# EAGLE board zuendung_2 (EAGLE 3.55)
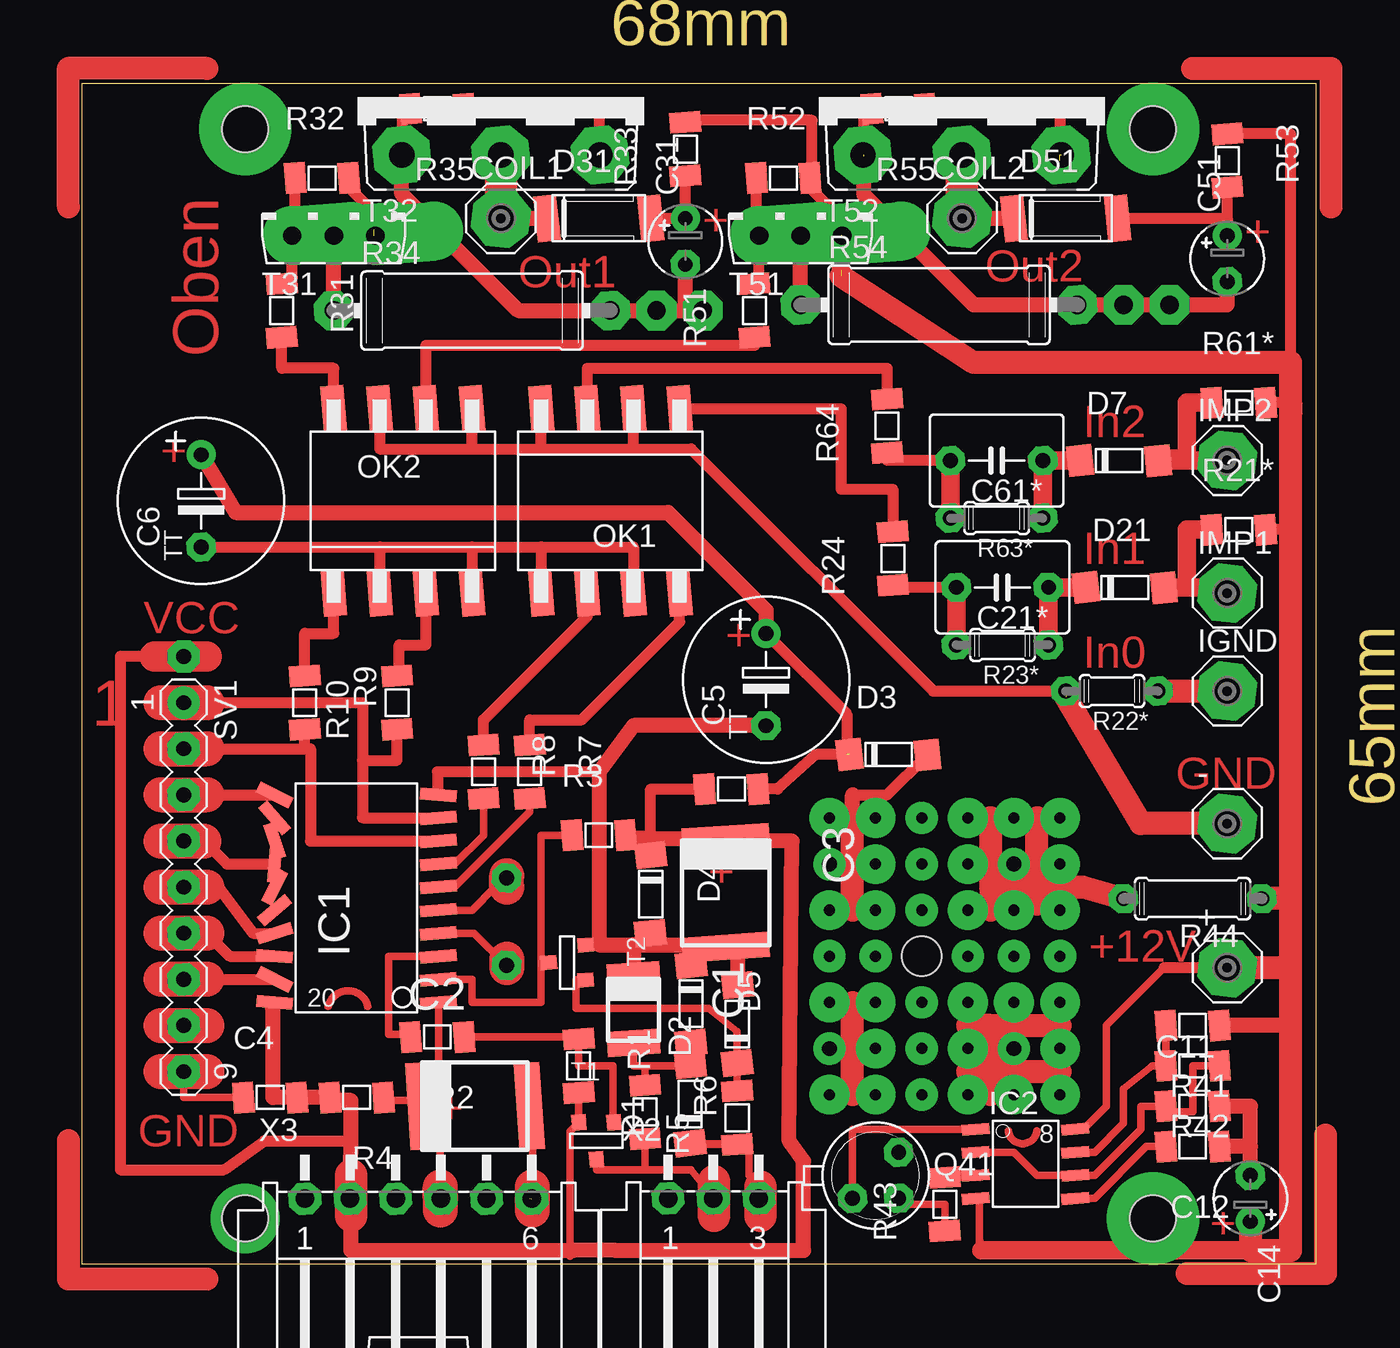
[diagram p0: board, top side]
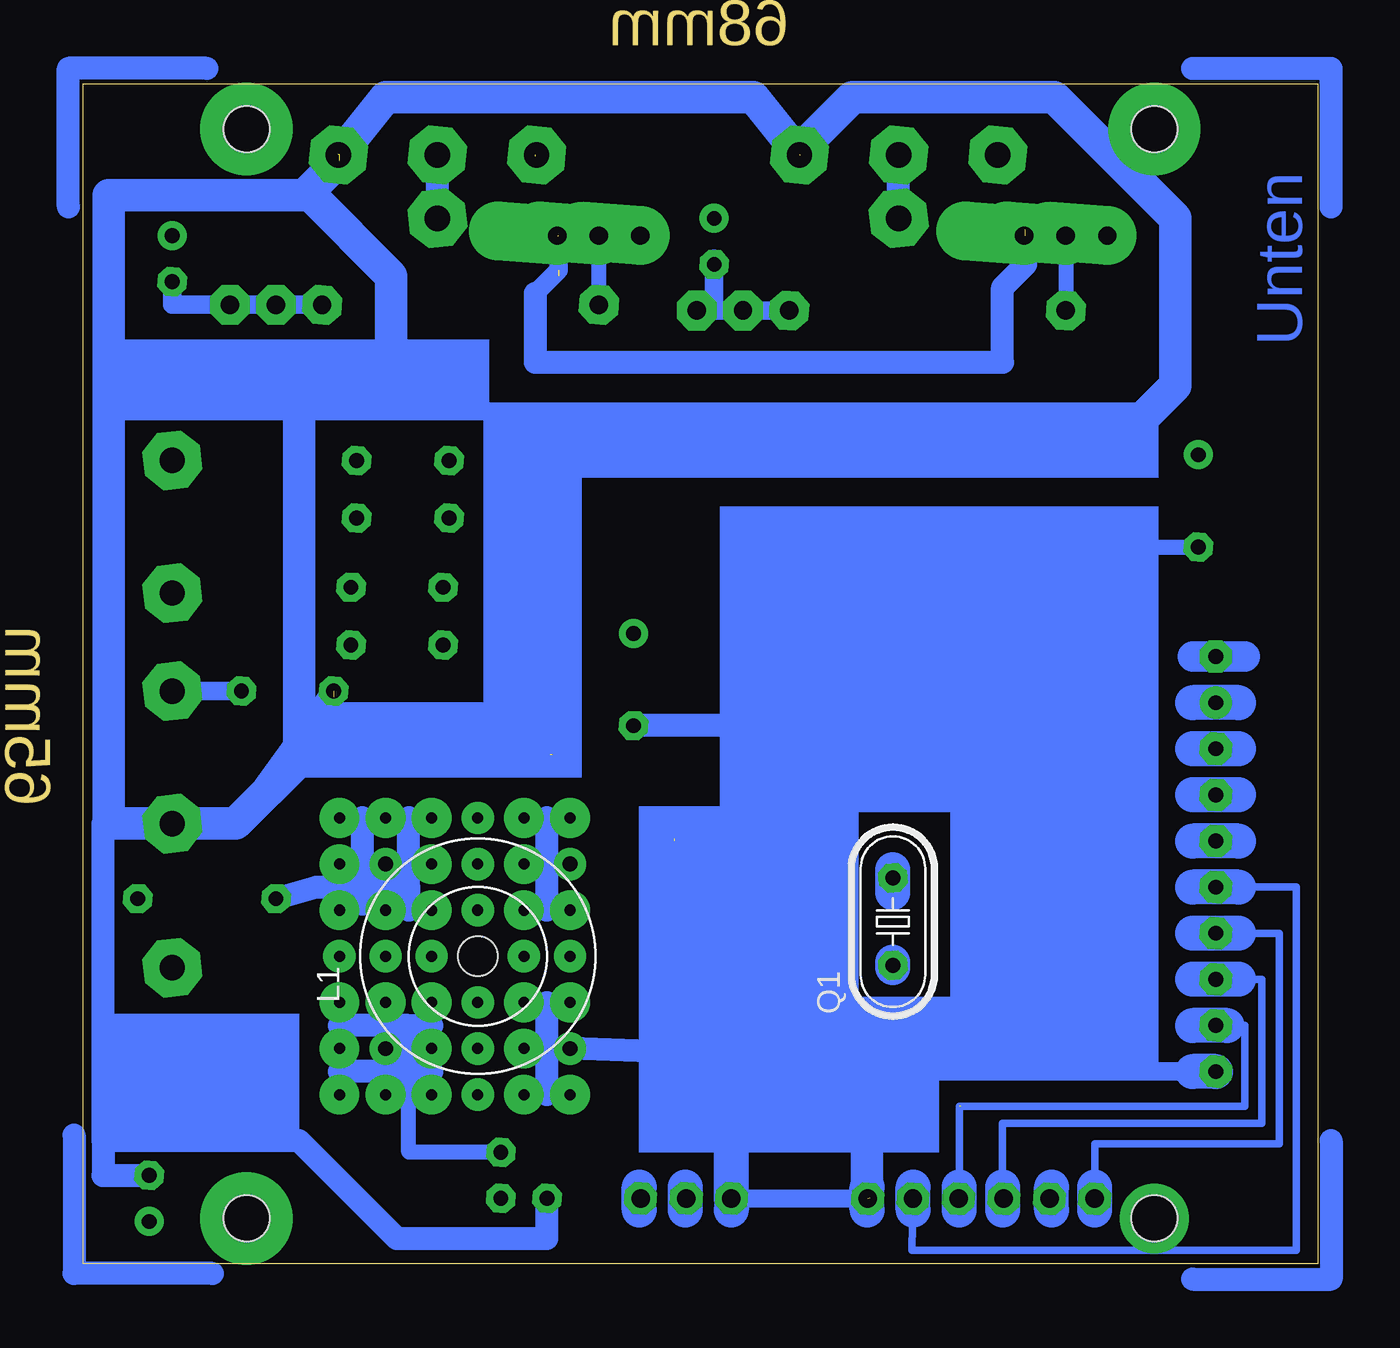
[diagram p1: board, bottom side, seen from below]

Size 68 x 65 mm. Coordinates in mm from the lower left corner, seen from the top.
Outline: 0,0 68,0 68,65 0,65 0,0
Copper layers used: Top, Bottom
Holes 2.54 mm at 9,2.5 59,2.5 59,62.5 9,62.5

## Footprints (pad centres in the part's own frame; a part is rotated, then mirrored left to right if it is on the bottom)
14E = drill 1.397 pad 3.175 octagon:  0,0
 = smd 1.4 x 2.9 rotated 3.8:  -1.8,0 | smd 1.4 x 2.9 rotated 4:  1.9,0
KO6X5 = smd 1.4 x 4.8 rotated 3.8:  -3,0 | smd 1.4 x 4.8 rotated 4:  3,0
06 = smd 1.143 x 1.702 rotated 4.4:  1.473,0 | smd 1.143 x 1.702 rotated 4.3:  -1.473,0
5D9 = drill 0.813 pad 1.6 octagon:  -2.54,0 | drill 0.813 pad 1.6 round:  2.54,0
2D4 = drill 0.813 pad 1.6 octagon:  -1.27,0 | drill 0.813 pad 1.6 round:  1.27,0
B5 = drill 0.813 pad 1.6 octagon:  -2.54,0;  2.54,0
D-80 = smd 1.397 x 1.702 rotated 6.6:  -2.388,0 | smd 1.397 x 1.702 rotated 5.7:  1.905,-0.025
LF = smd 1.27 x 2.54 rotated 6.6:  -2.857,0 | smd 1.27 x 2.54 rotated 5.7:  2.857,0
-20 = smd 0.66 x 2.007 rotated 4.3:  -5.08,-4.496;  6.35,-4.496 | smd 0.66 x 2.007 rotated 4.4:  -3.81,-4.496;  -5.08,4.521 | smd 0.66 x 2.007 rotated 4.5:  -2.54,-4.496 | smd 0.66 x 2.007 rotated 4.6:  -1.27,-4.496 | smd 0.66 x 2.007 rotated 4.7:  0,-4.496;  1.27,-4.496 | smd 0.66 x 2.007 rotated 4.8:  2.54,-4.496 | smd 0.66 x 2.007 rotated 4.9:  3.81,-4.496 | smd 0.66 x 2.007 rotated 5:  5.08,-4.496 | smd 0.66 x 2.007 rotated 49.3:  5.08,4.521 | smd 0.66 x 2.007 rotated 26.8:  6.35,4.521 | smd 0.66 x 2.007 rotated 71.8:  3.81,4.521 | smd 0.66 x 2.007 rotated 94.3:  2.54,4.521 | smd 0.66 x 2.007 rotated 116.8:  1.27,4.521 | smd 0.66 x 2.007 rotated 139.3:  0,4.521 | smd 0.66 x 2.007 rotated 161.8:  -1.27,4.521 | smd 0.66 x 2.007 rotated 184.3:  -2.54,4.521 | smd 0.66 x 2.007 rotated 206.8:  -3.81,4.521
-8 = smd 0.61 x 1.524 rotated 4.3:  -1.27,-2.743 | smd 0.61 x 1.524 rotated 4.9:  -1.27,2.743 | smd 0.61 x 1.524 rotated 4.4:  0,-2.743 | smd 0.61 x 1.524 rotated 4.5:  1.27,-2.743 | smd 0.61 x 1.524 rotated 4.8:  0,2.743 | smd 0.61 x 1.524 rotated 4.7:  1.27,2.743;  2.54,2.743 | smd 0.61 x 1.524 rotated 4.6:  2.54,-2.743
10X10 = drill 0.813 pad 1.778 round:  -5.08,5.08;  5.08,5.08;  5.08,-5.08;  -5.08,-5.08 | hole 2.184: 0,0
L08SO = smd 1.27 x 2.54 rotated 4.9:  -3.81,5.08 | smd 1.27 x 2.54 rotated 4.8:  -1.27,5.08 | smd 1.27 x 2.54 rotated 4.7:  1.27,5.08;  3.81,5.08 | smd 1.27 x 2.54 rotated 4.3:  -3.81,-5.08 | smd 1.27 x 2.54 rotated 4.4:  -1.27,-5.08 | smd 1.27 x 2.54 rotated 4.5:  1.27,-5.08 | smd 1.27 x 2.54 rotated 4.6:  3.81,-5.08
49U-V = drill 0.813 pad 1.6 octagon:  -2.413,0;  2.413,0
18 = drill 0.813 pad 1.6 octagon:  -1.27,-1.27;  1.27,-1.27;  1.27,1.27
04/5 = drill 0.813 pad 1.6 octagon:  -2.54,0;  2.54,0
14/15 = drill 1.016 pad 2.159 octagon:  -7.62,0;  7.62,0
07/7 = drill 0.813 pad 1.6 octagon:  -3.81,0;  3.81,0
09-1 = drill 0.813 pad 1.778 round:  -10.16,0 | drill 0.813 pad 1.778 octagon:  -7.62,0;  -5.08,0;  -2.54,0;  0,0;  2.54,0;  5.08,0;  7.62,0;  10.16,0
T-23 = smd 0.787 x 0.889 rotated 4.4:  0.991,1.016 | smd 0.787 x 0.889 rotated 4.3:  -0.94,1.016 | smd 0.787 x 0.889 rotated 4.5:  0.025,-1.016
126V = drill 1.016 pad 3.251 offset:  -2.286,-1.27;  0,-1.27;  2.286,-1.27
P3V = drill 1.397 pad 3.15 octagon:  -5.461,-3.175;  0,-3.175;  5.461,-3.175
FW3 = drill 1.016 pad 1.778 octagon:  0,1.905;  2.489,1.905;  5.004,1.905
FW6 = drill 1.016 pad 1.778 octagon:  0,1.905;  2.489,1.905;  5.004,1.905;  7.493,1.905;  10.008,1.905;  12.497,1.905

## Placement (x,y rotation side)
+  SE14E  [14E]  63.09,16.3 0 top
-  SE14E  [14E]  63.09,24.24 0 top
C1  2æ2/16  []  30.38,14.08 270 top
C2  22/16  [KO6X5]  21.65,8.68 0 top
C3  22/10  [KO6X5]  35.47,20.43 270 top
C4  100n  [06]  10.38,9.16 0 top
C5  470/10  [5D9]  37.69,32.18 90 top
C6  470/10  [5D9]  6.57,42.02 90 top
C11  2n7  [06]  61.18,8.68 0 top
C12  10n  [06]  61.18,6.46 180 top
C14  47/25  [2D4]  64.36,3.61 270 top
C21*  220n*  [B5]  50.7,37.26 180 top
C31  0,22  [2D4]  33.24,56.31 90 top
C51  0,22  [2D4]  63.09,55.36 90 top
C61*  220n*  [B5]  50.39,44.24 180 top
COIL1  SE14E  [14E]  23.08,57.58 0 top
COIL2  SE14E  [14E]  48.48,57.58 0 top
D1  LL4148  [D-80]  33.5,9.03 90 top
D2  LL4148  [D-80]  36.1,13.45 90 top
D3  LL4148  [D-80]  44.67,28.05 0 top
D4  5V1  [D-80]  31.34,20.11 270 top
D5  LL4148  [D-80]  33.56,14.08 270 top
D7  LL4148  [D-80]  57.37,44.24 0 top
D21  LL4148  [D-80]  57.69,37.26 0 top
D31  BYM10  [LF]  28.48,57.58 0 top
D51  BYM10  [LF]  54.2,57.58 0 top
IC1  AT90S2313  [-20]  15.14,19.48 90 top
IC2  ICM7555  [-8]  51.98,6.14 270 top
IGND  SE14E  [14E]  63.09,31.55 0 top
IMP1  SE14E  [14E]  63.09,36.94 0 top
IMP2  SE14E  [14E]  63.09,44.24 0 top
L1  T1:1/10  [10X10]  46.26,16.94 90 bottom
OK1  TLP759  [L08SO]  29.11,42.02 180 top
OK2  TLP759  [L08SO]  17.68,42.02 0 top
Q1  10.000  [49U-V]  23.4,18.84 90 bottom
Q41  BCY59  [18]  43.72,4.88 0 top
R1  4K7  [06]  27.37,10.91 270 top
R2  4K7  [06]  19.59,12.49 180 top
R3  4K7  [06]  28.48,23.61 0 top
R4  10K  [06]  15.14,9.16 180 top
R5  4K7  [06]  36.1,8.05 90 top
R6  4K7  [06]  31.02,8.37 270 top
R7  1K  [06]  24.67,27.1 270 top
R8  1k  [06]  22.13,27.1 270 top
R9  680  [06]  12.29,30.91 270 top
R10  680  [06]  17.37,30.91 90 top
R21*  12K*  [06]  63.72,40.44 0 top
R22*  0*  [04/5]  56.74,31.55 180 top
R23*  100K*  [04/5]  50.7,34.09 180 top
R24  330  [06]  44.67,38.85 90 top
R31  330  [06]  11.02,52.5 270 top
R32  1k  [06]  13.24,59.8 0 top
R33  270  [06]  33.24,61.39 90 top
R34  120/1  [14/15]  21.5,52.5 0 top
R35  1k2  [06]  19.59,63.61 180 top
R41  1k5  [06]  61.18,13.13 180 top
R42  1k5  [06]  61.18,10.91 180 top
R43  3K3  [06]  47.53,3.29 90 top
R44  56  [07/7]  61.18,20.11 180 top
R45  10  [06]  35.78,26.15 180 top
R51  330  [06]  37.05,52.5 90 top
R52  1k  [06]  38.64,59.8 0 top
R53  270  [06]  63.09,60.75 270 top
R54  120/1  [14/15]  47.21,52.82 0 top
R55  1k2  [06]  44.99,63.61 180 top
R61*  12k*  [06]  63.72,47.42 0 top
R63*  100k*  [04/5]  50.39,41.07 180 top
R64  330  [06]  44.35,46.15 90 top
SV1  MA09-1  [09-1]  5.62,20.75 270 top
T1  BC807  [T-23]  28.32,6.78 0 top
T2  BC817  [T-23]  26.73,16.62 270 top
T31  BD236_V  [126V]  13.88,57.9 0 top
T32  BD249_V  [P3V]  23.08,64.25 0 top
T51  BD236_V  [126V]  39.59,57.9 0 top
T52  BD249_V  [P3V]  48.48,64.25 0 top
U$8  [2]  -0.09,-0.21 0 top
U$9  [2]  67.85,0.11 90 top
U$10  [2]  68.17,65.2 180 top
U$11  [2]  -0.09,65.2 270 top
X2  MSFW3  [FW3]  32.29,1.7 0 top
X3  MSFW6  [FW6]  12.29,1.68 0 top

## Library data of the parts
+ - COIL1 COIL2 IGND IMP1 IMP2 = SOLPAD
C1-C4 C11 C12 D1-D5 D7 D21 D31 D51 R1-R10 R21* R24 R31-R33 R35 R41-R43 R45 R51-R53 R55 R61* R64 T1 T2 = SMD
C5 C6 C14 C31 C51 = CAP-TANT
C21* C61* = CAP
IC1 IC2 = SMD-IC
L1 = TRAFO-R
OK1 OK2 = OPTOCPL
Q1 = QUARTZ
Q41 T32 T52 = NPN
R22* R23* R34 R44 R54 R63* = R
SV1 = CON-LSTB
T31 T51 = PNP
U$8-U$11 = MARKS
X2 X3 = CON-MSF

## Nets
+12V: +. C14. IC2. R21*. R32. R33. R41. R44. R52. R53. R61*. T31. T51.
BT1: R1. R2. T1.
BT2: D2. R5. T2.
D21K: C21*. D21. R23*.
DGND: C1. C2. C3. C4. C5. C6. D2. D4. D5. IC1. L1. OK1. OK2. SV1. T2. X2. X3.
GND: -. C11. C12. C14. IC2. OK1. OK2. Q41. R22*. R35. R55. T32. T52.
INT0: OK1. R7.
MISO: IC1. SV1. X3.
MOSI: IC1. SV1. X3.
N$1: C31. D31. R33.
N$2: R31. R32. T31.
N$3: OK2. R31.
N$4: IC2. R43.
N$5: C12. IC2.
N$6: L1. R44.
N$7: C5. C6. D3. R45.
N$8: OK1. R24.
N$9: R34. T31.
N$10: C31. R34. R35. T32.
N$11: D3. L1.
N$14: C11. IC2. R42.
N$15: IC2. R41. R42.
N$16: C1. D1. D5. R6.
N$29: C21*. R23*. R24.
N$46: L1. Q41.
N$48: Q41. R43.
N$92: OK2. R51.
N$93: OK2. R10.
N$94: OK1. R64.
N$96: IC1. R8.
N$102: OK1. R8.
N$103: R54. T51.
N$104: R51. R52. T51.
N$105: COIL2. D51. T52.
N$106: C51. R54. R55. T52.
N$107: C51. D51. R53.
N$108: D7. IMP2. R61*.
N$109: C61*. R63*. R64.
N$111: C61*. D7. R63*.
OUT0: OK2. R9.
PB2: IC1. SV1.
PD0: IC1. R3. T2.
PD1: IC1. R2.
PD2: IC1. R7.
PD4: IC1. R9. SV1.
PD5: IC1. R10. SV1.
PD6: IC1. SV1.
RESET: C2. IC1. R4. SV1. X3.
RXD: D1. R5. X2.
SCK: IC1. SV1. X3.
TXD: R6. T1. X2.
VCC: C3. C4. D4. IC1. R1. R3. R4. R45. T1. X3.
X6: COIL1. D31. T32.
X21: D21. IMP1. R21*.
X22: IGND. R22*.
XTAL1: IC1. Q1.
XTAL2: IC1. Q1.

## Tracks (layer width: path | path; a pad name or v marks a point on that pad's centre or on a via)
+12V  (3 unrouted)
  Top 0.406: 49.44,1.38 49.44,1.06 | 49.44,1.38 49.55,0.75 | 49.23,3.61 49.44,3.61 49.44,1.38 | 54.72,7.41 55.15,7.41 56.42,8.68 56.42,13.13 59.59,16.3
  Top 0.61: 66.58,47.42 65.2,47.42 | 66.58,40.44 65.2,40.44 | +. 59.59,16.3 | 41.81,57.58 40.11,59.28 40.11,59.8 40.23,59.8 40.23,62.98 33.24,62.98 33.24,62.86 | 14.71,59.8 14.71,59.28 16.1,57.9 16.1,56.63 T31. | R53. 66.58,62.23 66.58,49.64
  Top 0.813: 66.58,13.13 R41.
  Top 1.016: 49.55,0.75 64.36,0.75 | 41.81,54.41 41.81,56.63 41.81,57.58
  Top 1.27: C14. 64.36,0.75 66.58,0.75 66.58,13.13 66.58,16.3 | 66.58,20.11 66.58,40.44 66.58,47.42 | 66.58,47.42 66.58,46.78 | 66.58,47.42 66.58,49.64 49.12,49.64 41.81,54.41 | 66.58,20.11 64.99,20.11 | 66.58,16.3 66.58,20.11 | 66.58,16.3 +.
  Bottom 1.016: 43.09,53.45 41.81,54.72 41.81,56.94
  Bottom 1.27: 43.09,53.45 43.09,49.64 17.37,49.64 17.37,53.77 16.1,55.04 16.1,56.94
BT1
  Top 0.406: 27.37,12.5 27.53,12.5 | 27.37,12.5 R1. 27.37,10.91 29.27,10.91 29.27,7.73 29.31,7.73 29.31,7.8 | R2. | R2. 27.37,12.5
BT2
  Top 0.406: 36.1,9.52 36.1,11.06 36.1,12.81 34.51,14.08 27.21,14.08 27.21,15.63 27.75,15.63
D21K
  Top 1.016: 55.3,37.26 53.24,37.26 53.24,34.09
DGND  (1 unrouted)
  Top 0.406: SV1. 5.62,9.16 C4. | C2. 24.83,10.43 24.83,3.76 24.67,3.61 | 27.75,17.56 28.23,17.57 28.48,17.57 | 31.66,17.57 D4. | 35.47,17.57 36.12,17.57
  Top 0.61: 6.57,39.48 16.41,39.48 | 16.41,39.48 16.41,36.94 | 16.41,39.48 21.5,39.48 | 21.5,39.48 OK2. | 21.5,39.48 25.3,39.48 | 25.3,39.48 25.3,36.94 | 25.3,39.48 30.38,39.48 30.38,36.94 | 28.48,27.1 19.59,27.1 19.59,25.83 19.64,25.83
  Top 0.813: 36.12,17.57 D2. | 30.38,17.57 30.38,15.88 | 30.38,17.57 31.66,17.57 35.47,17.57 | 30.38,17.57 28.48,17.57 28.48,27.1 30.38,29.64 37.69,29.64 | 35.47,17.57 C3. | 33.56,16.47 33.56,17.57 35.47,17.57
  Bottom 0.406: 24.83,3.61 X3. 24.99,3.59 24.99,3.61 24.67,3.61 | 32.29,3.61 32.29,11.54
  Bottom 0.813: 6.57,39.48 9.43,39.48 9.43,36.31 15.14,29.64 37.69,29.64
  Bottom 1.016: 6.89,10.59 24.83,10.59 | X3. 32.29,3.61 | 32.29,21.38 28.48,21.38
  Bottom 1.27: 37.69,29.64 32.29,29.64 32.29,21.38 | 32.29,11.54 L1.
  Bottom 1.778: 24.83,10.59 24.83,3.61
  Bottom 1.93: 32.29,21.38 32.29,3.61 32.29,2.97 | SV1. 6.89,10.59
GND  (4 unrouted)
  Top 0.406: 42.45,3.61 42.45,7.41 49.23,7.41 49.44,7.41
  Top 0.61: 25.3,44.88 30.38,44.88 | 25.3,44.88 OK1. | 21.5,44.88 25.3,44.88 | 21.5,44.88 21.5,47.1 | 21.5,44.88 16.41,44.88 16.41,47.1 | 30.38,44.88 30.38,47.1 | 30.38,44.88 33.56,44.88 46.9,31.55 R22*. | R35. 28.48,63.61 28.48,61.07 | R55. 53.88,63.61 53.88,60.75
  Top 0.813: 62.66,8.68 64.36,8.68 64.36,6.46 | 64.36,6.46 C12. | 64.36,4.88 64.36,6.46
  Top 1.27: 54.2,31.23 58.33,24.24 -.
  Bottom 1.27: R22*. 59.28,24.51 | 66.9,6.78 66.9,24.24 66.58,24.24 | 66.9,6.78 66.9,4.88 64.36,4.88 | 42.45,3.61 42.45,1.38 50.7,1.38 56.1,6.78 66.9,6.78 | T32. 28.48,61.07 | 53.56,61.07 T52.
  Bottom 1.778: T32. 31.08,64.25 51.34,64.25 53.88,61.07 | 63.41,24.24 66.58,24.24 66.58,58.85 55.78,58.85 53.56,61.07 | 63.41,24.24 -. | 63.41,24.24 59.59,24.24 56.1,27.73 56.1,48.37
INT0
  Top 0.61: 32.92,36.94 32.92,35.35 27.53,29.96 24.67,29.96 R7.
MISO
  Top 0.406: 5.62,18.21 6.89,18.21 | 10.62,16.94 10.7,16.94
  Top 0.61: 6.89,18.21 8.16,16.94 10.62,16.94
  Top 1.93: 6.89,18.21 4.35,18.21
  Bottom 0.406: 5.62,18.21 4.35,18.21 2.13,18.21 2.13,6.62 12.29,6.62 12.29,3.59
  Bottom 1.93: 4.35,18.21 6.89,18.21
MOSI
  Top 0.406: 5.62,20.75 7.53,20.75
  Top 0.61: 7.53,20.75 9.43,18.21 10.62,18.21
  Bottom 0.406: 22.3,3.59 22.36,0.75 1.17,0.75 1.17,20.75 4.35,20.75 5.62,20.75
  Bottom 1.93: 4.35,20.75 6.89,20.75
N$1
  Top 0.61: D31. C31. R33.
N$2
  Top 0.61: R32. 11.77,56.74 11.65,56.63 11.59,56.63 11.59,54.34 11.02,53.77 R31.
N$3
  Top 0.61: 11.02,51.03 11.02,49.33 13.88,49.33 13.88,47.1
N$4
  Top 0.406: 47.53,4.76 47.53,4.88
  Top 0.61: 49.44,4.88 49.23,4.88 47.53,4.88
N$5
  Top 0.406: 59.71,6.46 58.64,6.46 55.78,3.61 IC2. 54.52,3.61
N$6
  Top 0.813: 51.66,20.75 51.34,21.07 51.34,22.02
  Top 1.27: R44. 55.15,20.75 51.66,20.75
  Bottom 1.27: 54.2,20.75 55.15,20.75 R44.
N$7  (1 unrouted)
  Top 0.61: R45. 38.32,26.15 40.43,28.05 42.13,28.05 42.13,30.27 C5.
  Top 0.813: C5. 37.69,35.99 32.29,41.39 8.48,41.39 C6.
N$8
  Top 0.61: 32.92,47.1 41.81,47.1 41.81,42.66 44.67,42.66 44.67,40.32
N$9
  Top 0.813: 13.88,52.5 13.88,56.63
  Bottom 0.813: 13.88,52.5 13.56,52.5 13.88,52.82 13.88,56.63
N$10  (via drill 1.02 pad 2.18)
  Top 0.61: 18.12,63.61 17.68,63.61 17.68,61.07
  Top 0.813: 17.68,61.07 17.62,61.07 17.62,58.91 24.04,52.5 R34. v34.2,52.5 33.24,52.5 33.24,55.04
  Bottom 1.016: R34. 33.24,52.5 | 33.24,55.36 33.24,55.04 33.24,52.5 | 33.24,52.5 v34.2,52.5
N$11
  Top 0.61: D3. 44.35,25.83 42.45,25.83
  Top 0.813: 42.45,25.83 42.45,22.02 41.18,22.02
N$12  (via drill 0.61 pad 2.18)
  other vias: 43.72,22.02
N$13
  Top 1.93: 4.35,20.75 6.89,20.75
N$14
  Top 0.406: R42. 61.18,10.91 61.18,8.37 59.59,8.37 59.59,8.68 C11. 58.33,8.68 58.33,7.41 55.78,4.88 54.52,4.88 | 49.23,6.14 51.34,6.14 52.61,4.88 54.52,4.88 | 54.52,4.88 54.72,4.88
N$15
  Top 0.406: 59.71,10.91 59.71,13.13 | 59.71,10.91 59.59,10.91 | 59.71,10.91 58.96,10.91 57.37,9.64 57.37,7.73 55.78,6.14 54.72,6.14 54.52,6.14
N$16
  Top 0.406: 31.02,10.91 30.38,10.91 C1. | 31.02,10.91 R6. | 31.02,10.91 33.56,10.91
  Top 0.813: D1. 33.56,10.91 33.53,10.91 D5.
N$17
  Top 1.93: 4.35,13.13 6.89,13.13
N$18
  Top 1.93: 4.35,10.59 6.89,10.59
N$19
  Top 1.93: 23.4,16.78 23.4,16.3
N$20  (via drill 0.61 pad 2.18)
  other vias: 48.8,22.02
N$21
  Bottom 1.93: 12.29,2.97 12.29,4.24
N$22
  Bottom 1.93: 14.67,2.97 14.67,4.24
N$23
  Bottom 1.93: 19.75,2.97 19.75,4.24
N$24
  Bottom 1.93: 22.29,2.97 22.29,4.24
N$25
  Bottom 1.93: 24.83,2.97 24.83,4.24
N$26
  Bottom 1.93: 34.83,2.97 34.83,4.24
N$27
  Bottom 1.93: 37.37,2.97 37.37,4.24
N$28
  Bottom 1.93: 4.35,30.91 6.89,30.91
N$29
  Top 0.61: R24. 44.67,37.26 C21*.
  Top 1.016: R23*. C21*.
N$30
  Bottom 1.93: 4.35,28.37 6.89,28.37
N$31
  Bottom 1.93: 4.35,25.83 6.89,25.83
N$32
  Bottom 1.93: 4.35,23.29 6.89,23.29
N$33
  Bottom 1.93: 23.4,20.43 23.4,21.7
N$34
  Bottom 1.93: 23.4,16.3 23.4,16.62
N$35  (via drill 1.02 pad 2.18)
  other vias: 31.66,52.5
N$37  (via drill 1.02 pad 2.18)
  other vias: 57.37,52.82
N$38  (via drill 1.02 pad 2.18)
  other vias: 59.91,52.82
N$39  (via drill 0.61 pad 2.18)
  other vias: 51.34,24.56
N$40
  Top 1.93: 24.83,2.97 24.83,4.24
N$41  (via drill 1.27 pad 5.08)
  other vias: 59,2.5
N$42  (via drill 1.27 pad 5.08)
  other vias: 59,62.5
N$43  (via drill 1.27 pad 5.08)
  other vias: 9,62.5
N$44  (via drill 1.27 pad 3.81)
  other vias: 9,2.5
N$45
  Top 1.778: 34.83,2.65 34.83,4.56
N$46
  Bottom 0.813: Q41. 50.07,6.14 50.07,11.86 51.34,11.86 51.66,11.86
N$47  (via drill 0.61 pad 2.18)
  other vias: 53.88,22.02
N$48
  Top 0.406: R43. 47.53,3.29 44.99,3.29 44.99,3.61
N$49  (via drill 0.61 pad 2.18)
  other vias: 48.8,19.48
N$50  (via drill 0.61 pad 2.18)
  other vias: 51.34,19.48
N$51  (via drill 0.61 pad 2.18)
  other vias: 53.88,19.48
N$52  (via drill 0.61 pad 2.18)
  other vias: 41.18,19.48
N$53  (via drill 0.61 pad 2.18)
  other vias: 43.72,19.48
N$54  (via drill 0.61 pad 2.18)
  other vias: 41.18,14.4
N$55  (via drill 0.61 pad 2.18)
  other vias: 43.72,14.4
N$56  (via drill 0.61 pad 2.18)
  other vias: 48.8,14.4
N$57  (via drill 0.61 pad 2.18)
  other vias: 51.34,14.4
N$58  (via drill 0.61 pad 2.18)
  other vias: 53.88,14.4
N$59  (via drill 0.61 pad 2.18)
  other vias: 48.8,11.86
N$60  (via drill 0.61 pad 2.18)
  other vias: 43.72,11.86
N$61  (via drill 0.61 pad 2.18)
  other vias: 41.18,9.32
N$62  (via drill 0.61 pad 2.18)
  other vias: 43.72,9.32
N$63  (via drill 0.61 pad 2.18)
  other vias: 43.72,24.56
N$64  (via drill 0.61 pad 2.18)
  other vias: 48.8,24.56
N$65  (via drill 0.61 pad 2.18)
  other vias: 41.18,24.56
N$66  (via drill 0.61 pad 2.18)
  other vias: 53.88,11.86
N$67  (via drill 0.61 pad 2.18)
  other vias: 48.8,9.32
N$68
  Top 1.27: 42.45,19.48 42.45,24.56
N$69
  Top 1.27: 50.07,20.75 50.07,24.56 | 50.07,20.75 50.07,19.48 | 50.07,20.75 53.88,20.75
N$70
  Top 1.27: 42.45,9.32 42.45,14.4
N$71
  Top 1.27: 50.07,13.13 48.8,13.13 | 50.07,13.13 53.88,13.13 | 50.07,9.32 50.07,13.13
N$72
  Bottom 1.27: 42.45,19.48 42.45,24.56
N$73
  Bottom 1.27: 50.07,20.75 50.07,24.56 | 50.07,20.75 50.07,19.48 | 50.07,20.75 53.88,20.75
N$74
  Bottom 1.27: 42.45,9.32 42.45,14.4
N$75
  Bottom 1.27: 50.07,13.13 48.8,13.13 | 50.07,13.13 53.88,13.13 | 50.07,9.32 50.07,13.13
N$76
  Bottom 1.778: 9.43,46.78 7.84,48.37 7.84,57.58 14.51,64.25 25.62,64.25 28.48,61.39
N$77  (via drill 0.61 pad 2.18)
  other vias: 51.34,9.32
N$78  (via drill 0.61 pad 2.18)
  other vias: 53.88,9.32
N$79  (via drill 0.61 pad 1.78)
  other vias: 46.26,24.56
N$80  (via drill 0.61 pad 1.78)
  other vias: 46.26,22.02
N$81  (via drill 0.61 pad 1.78)
  other vias: 46.26,19.48
N$82  (via drill 0.61 pad 1.78)
  other vias: 46.26,14.4
N$83  (via drill 0.61 pad 1.78)
  other vias: 46.26,11.86
N$84  (via drill 0.61 pad 1.78)
  other vias: 46.26,9.32
N$85  (via drill 0.61 pad 1.78)
  other vias: 48.8,16.94
N$86  (via drill 0.61 pad 1.78)
  other vias: 51.34,16.94
N$87  (via drill 0.61 pad 1.78)
  other vias: 53.88,16.94
N$88  (via drill 0.61 pad 1.78)
  other vias: 41.18,16.94
N$89  (via drill 0.61 pad 1.78)
  other vias: 43.72,16.94
N$90  (via drill 0.61 pad 1.78)
  other vias: 46.26,16.94
N$91
  Top 1.778: 37.37,2.65 37.37,4.24
N$92
  Top 0.61: 18.95,47.1 18.64,47.1 18.95,47.42 18.95,50.59 37.05,50.59 R51.
N$93
  Top 0.61: 18.95,36.94 18.95,34.09 17.48,34.09 17.48,32.61 17.37,32.5 17.37,32.38
N$94
  Top 0.61: 44.35,47.62 44.35,49.33 27.84,49.33 27.84,47.1
N$95  (via drill 0.81 pad 1.78)
  other vias: 5.62,33.45
N$96
  Top 0.406: 22.13,25.63 22.13,23.61 20.54,22.02 19.64,22.02
N$97
  Top 1.27: 48.8,10.59 53.88,10.59
N$98  (via drill 0.61 pad 2.18)
  other vias: 53.88,24.56
N$99
  Top 1.27: 52.61,19.8 52.61,24.56
N$100
  Bottom 1.27: 52.61,24.56 52.61,20.11 52.61,19.8
N$101
  Bottom 1.27: 48.8,10.59 53.88,10.59
N$102
  Top 0.61: 27.84,36.94 27.84,35.67 22.13,29.96 R8. 21.81,28.37
N$103
  Top 0.813: 39.59,52.82 39.59,56.63
  Bottom 0.813: 39.59,52.82 39.59,56.63
N$104
  Top 0.61: R52. 37.17,56.83 37.37,56.63 37.31,56.63 37.31,54.02 37.05,53.77 37.05,53.97
N$105
  Top 0.813: COIL2. 51.34,57.58
  Top 1.778: COIL2. 48.48,61.07
  Bottom 1.27: 48.48,57.26 COIL2. 48.48,61.07
N$106  (1 unrouted)
  Top 0.61: 43.09,61.01 43.09,60.75 | 43.02,61.07 43.09,61.01 | 43.52,63.61 43.09,63.18 43.09,61.01
  Top 0.813: 43.09,61.07 43.09,58.85 49.12,52.82 R54. 63.09,52.82 63.09,54.09
  Bottom 1.016: R54. 63.09,52.82 63.09,54.09
N$107
  Top 0.61: 63.09,59.28 C51. 63.09,57.58 D51.
N$108
  Top 0.61: 60.87,44.56 59.91,44.56 59.59,44.24
  Top 1.016: D7. 59.3,44.24 59.59,44.24 IMP2. | R61*. 60.87,47.42 60.87,44.56
N$109
  Top 0.61: R64. 44.35,44.24 C61*.
  Top 1.016: R63*. C61*.
N$110
  Top 1.676: 4.03,33.45 6.89,33.45
N$111
  Top 1.016: 52.93,44.24 52.61,44.24 | 52.93,44.24 54.98,44.24 | 52.93,41.07 52.93,44.24
N$113
  Bottom 1.676: 4.03,33.45 6.89,33.45
N$114
  Bottom 1.778: 55.47,58.85 51.02,54.41 51.02,49.96
OUT0
  Top 0.61: R9. 12.29,34.72 13.88,34.72 13.88,36.94
PB2
  Top 0.406: 6.73,23.29 5.62,23.29 | 10.62,22.02 10.7,22.02
  Top 0.61: 6.73,23.29 8,22.02 10.62,22.02
  Top 1.93: 4.35,23.29 6.73,23.29
PD0
  Top 0.406: R3. 25.3,23.61 25.3,16.62 | 25.3,16.62 25.3,16.46 | T2. 25.3,16.6 25.3,16.62 | 25.3,16.62 25.3,14.4 21.5,14.4 21.5,15.67 19.64,15.67
PD1
  Top 0.406: 19.64,16.94 16.89,16.94 16.89,12.65 18.12,12.65 18.12,12.5
PD2
  Top 0.406: 19.59,20.75 19.64,20.75 20.54,20.75 24.67,24.88 24.67,25.63
PD4
  Top 0.406: 6.89,28.37 5.62,28.37 | 19.64,23.29 19.91,23.29 | 12.29,28.37 12.61,28.37
  Top 0.61: 12.61,28.37 12.61,23.29 19.64,23.29 | 12.29,29.44 12.29,28.37 6.89,28.37
  Top 1.93: 4.35,28.37 6.89,28.37
PD5
  Top 0.406: 6.89,30.91 5.62,30.91
  Top 0.61: 6.89,30.91 15.46,30.91 15.46,27.73 | 15.46,27.73 15.46,24.56 19.64,24.56 | 15.46,27.73 17.37,27.73 R10.
  Top 1.93: 4.35,30.91 6.89,30.91
PD6
  Top 0.406: 10.62,25.83 10.7,25.83 | 6.89,25.83 5.62,25.83
  Top 0.61: 6.89,25.83 10.62,25.83
  Top 1.93: 4.35,25.83 6.89,25.83
RESET  (1 unrouted)
  Top 0.406: 18.65,8.68 18.65,9 16.62,9 R4. | 18.65,8.68 18.64,8.68 | 19.64,14.4 19.64,8.68 18.65,8.68 | 19.75,3.76 19.75,8.68 18.65,8.68 | 19.59,3.59 19.59,3.29 | 19.78,3.59 19.59,3.59 | 19.75,3.61 19.59,3.61 19.59,3.59
  Top 1.93: 19.75,4.24 19.75,3.76 19.75,3.61 19.75,2.97
  Bottom 0.406: 5.62,13.13 4.99,13.13 4.03,13.13 4.03,8.68 19.75,8.68 19.75,3.76
  Bottom 1.93: 4.99,13.13 6.89,13.13
RXD
  Top 0.406: 33.56,6.58 33.5,6.64 36.73,6.61 36.73,4.88 37.37,3.61 X2. | 33.56,6.58 R5. | 33.56,6.58 33.56,6.46
SCK
  Top 0.406: 5.62,15.67 6.89,15.67
  Top 0.61: 6.89,15.67 10.62,15.67
  Top 1.93: 6.89,15.67 4.35,15.67
  Bottom 0.406: 17.37,4.24 17.37,7.73 3.08,7.73 3.08,15.67 4.35,15.67 5.62,15.67 | 17.37,3.61 17.29,3.59
  Bottom 1.93: 17.37,4.24 17.37,3.61 17.37,2.97 | 4.35,15.67 6.89,15.67
TXD
  Top 0.406: 34.78,3.61 34.83,3.61 33.56,5.19 31.02,5.19 | 31.02,5.19 31.02,6.89 | T1. 28.35,5.19 31.02,5.19
VCC  (1 unrouted)
  Top 0.406: 14.78,3.76 14.67,3.76 | 14.78,3.76 14.78,3.59 | 14.83,2.65 14.83,3.76 14.78,3.76 | 31.34,23.45 31.34,23.43 | 29.95,23.61 30.11,23.45 | 27.37,7.73 27.38,7.73 27.38,7.8 26.89,7.31 26.89,0.43 27.06,0.75 | 27.37,7.73 27.37,9.43 | 27.37,7.73 27.21,7.73 | 29.43,0.75 | 29.42,0.75 29.43,0.75
  Top 0.61: 34.31,26.15 31.34,26.15 31.34,23.45 | 10.54,14.24 10.38,14.08 IC1. | 3.71,33.45 2.13,33.45 2.13,5.19 7.84,5.19 10.06,6.78 14.83,6.78
  Top 0.813: 35.47,23.43 31.34,23.43 31.34,22.5 | 29.43,0.75 39.75,0.75 39.75,5.67 38.96,6.78 39.12,23.29 35.47,23.29 | 14.83,2.65 14.83,0.75 27.06,0.75 29.42,0.75 | 10.54,14.24 10.54,9.16 11.86,9.16 13.67,9.16 13.67,9 14.83,9 14.83,6.78 14.78,3.76 | 30.11,23.45 31.34,23.45
  Top 1.778: 14.83,2.65 14.83,4.88
X6
  Top 0.813: COIL1. 25.62,57.58
  Top 1.778: 23.08,61.07 COIL1.
  Bottom 1.27: 23.08,61.07 23.08,57.26 22.77,56.94
X21
  Top 0.61: D21. 59.59,36.94 59.91,37.26 60.87,37.26
  Top 1.016: D21. 63.09,37.23 IMP1. | R21*. 60.87,40.44 60.87,37.26
X22
  Top 1.27: 59.28,31.55 IGND.
  Bottom 1.016: 59.28,31.55 IGND.
XTAL1
  Top 0.406: 19.64,19.48 21.5,19.48 22.77,20.75 23.4,20.75 Q1. 23.4,21.38
  Top 1.93: 23.4,20.75 23.4,21.38
XTAL2
  Top 0.406: 19.59,18.21 19.64,18.21 21.62,18.21 23.4,16.43
(copper drawn outside any net)
  Top 0.406: 13.56,14.08 arc-164 15.78,14.08 | 51.02,7.41 arc180 52.61,7.41
  shapes: Bottom area x10

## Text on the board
Top: + | + | Out1 | Out2 | Oben | In2 | + | In1 | VCC | + | In0 | 1 | GND | + | +12V | + | GND | +
Bottom: Unten
Dimension: 68mm | 65mm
